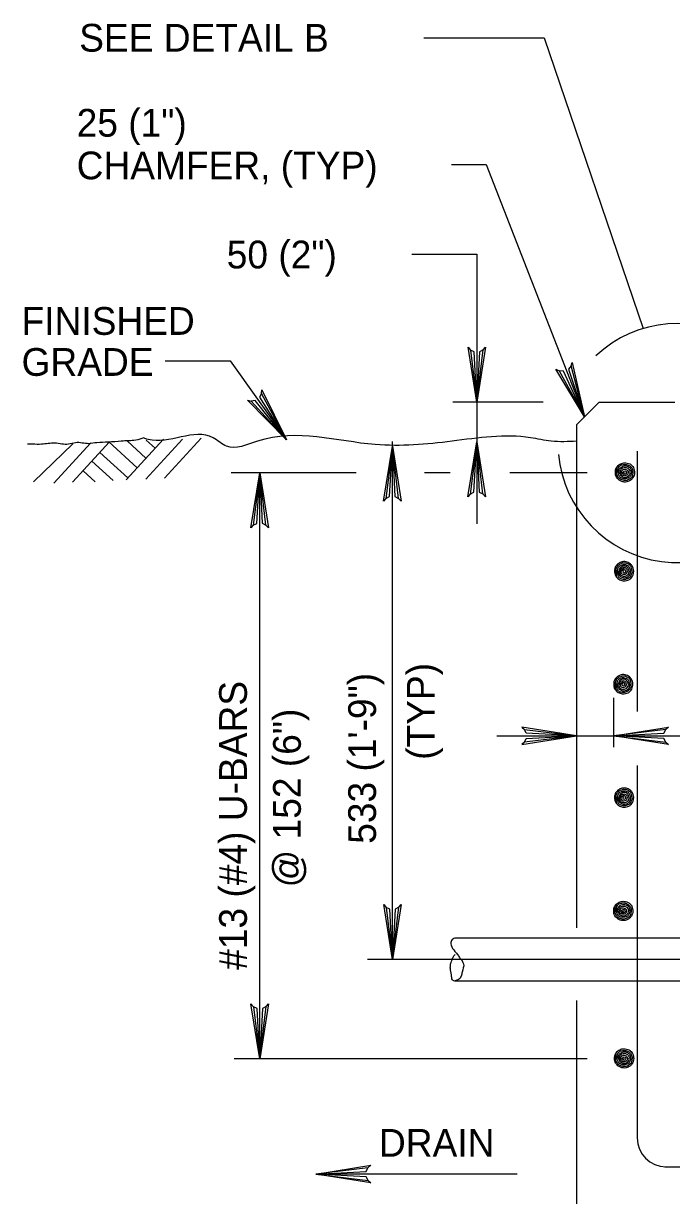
# Model space of a CAD drawing. Extents: x 638455 to 640199, y 298558 to 299152.
# Drawn here: x 638543.6 to 638622.1, y 298702.3 to 298844.2 of the extents above; entities that cross this region are included whole.
import ezdxf

# ---------------------------------------------------------------- set-up
doc = ezdxf.new("R2010")
doc.units = 0
for name, color, linetype in [('1', 7, 'Continuous'), ('2', 7, 'Continuous'), ('3', 7, 'Continuous')]:
    doc.layers.add(name, color=color, linetype=linetype)

msp = doc.modelspace()

# ---------------------------------------------------------------- linework, layer by layer
at = {"layer": '1'}
msp.add_arc((638622.78, 298793.39), 14.46, 185.4387, 133.0087, dxfattribs=at)
at = {"layer": '2'}
for p, q in [((638592.11, 298842.42), (638606.65, 298842.42)), ((638606.65, 298842.42), (638618.63, 298807.24)), ((638595.46, 298827.12), (638599.64, 298827.12)), ((638599.64, 298827.12), (638611.55, 298796.56)), ((638590.63, 298816.24), (638598.49, 298816.24)), ((638598.49, 298816.24), (638598.49, 298798.33)), ((638560.78, 298803.33), (638568.64, 298803.33)), ((638568.64, 298803.33), (638575.46, 298793.78)), ((638606.53, 298798.33), (638595.61, 298798.33)), ((638610.59, 298795.6), (638613.33, 298798.33)), ((638613.33, 298798.33), (638622.49, 298798.33)), ((638610.59, 298795.6), (638610.59, 298734.74)), ((638544.84, 298788.71), (638549.58, 298793.3)), ((638547.31, 298788.55), (638551.79, 298793.44)), ((638549.57, 298788.65), (638554.04, 298793.54)), ((638553.94, 298793.54), (638557.4, 298790.38)), ((638556.06, 298788.94), (638560.56, 298793.86)), ((638556.2, 298793.64), (638558.45, 298791.58)), ((638558.44, 298789.04), (638562.87, 298793.88)), ((638558.48, 298793.74), (638559.55, 298792.76)), ((638560.69, 298789.14), (638565.13, 298793.98)), ((638588.29, 298730.89), (638588.29, 298793.59)), ((638552.87, 298792.26), (638556.25, 298789.17)), ((638617.91, 298792.41), (638617.91, 298760.91)), ((638551.91, 298791.21), (638554.48, 298788.86)), ((638550.83, 298790.03), (638552.3, 298788.69)), ((638583.92, 298789.78), (638568.78, 298789.78)), ((638572.22, 298718.88), (638572.22, 298789.78)), ((638595.27, 298789.78), (638592.17, 298789.78)), ((638611.86, 298789.78), (638602.49, 298789.78)), ((638615.07, 298762.55), (638615.07, 298756.61)), ((638600.94, 298757.98), (638615.07, 298757.98)), ((638615.07, 298757.98), (638634.48, 298757.98)), ((638617.91, 298754.37), (638617.91, 298709.3)), ((638630.69, 298733.5), (638595.84, 298733.5)), ((638630.69, 298733.5), (638599.56, 298733.5)), ((638590.79, 298730.89), (638585.29, 298730.89)), ((638626.91, 298730.89), (638590.79, 298730.89)), ((638630.69, 298728.28), (638595.84, 298728.28)), ((638630.69, 298728.28), (638599.56, 298728.28)), ((638610.59, 298725.94), (638610.59, 298697.04)), ((638611.86, 298718.88), (638569.13, 298718.88)), ((638621.25, 298705.81), (638725.26, 298705.81))]:
    msp.add_line(p, q, dxfattribs=at)
for points in [[(638599.29, 298804.66), (638598.83, 298804.43), (638598.49, 298798.33), (638599.29, 298804.66), (638599.57, 298804.99), (638598.49, 298798.33), (638598.19, 298804.42), (638597.74, 298804.64), (638598.49, 298798.33), (638597.44, 298804.99), (638597.74, 298804.64)], [(638609.93, 298802.73), (638609.59, 298802.34), (638611.55, 298796.56), (638609.93, 298802.73), (638610.06, 298803.13), (638611.55, 298796.56), (638609, 298802.1), (638608.49, 298802.13), (638611.55, 298796.56), (638608.08, 298802.34), (638608.49, 298802.13)], [(638572.43, 298799.39), (638572.2, 298798.93), (638575.46, 298793.78), (638572.43, 298799.39), (638572.47, 298799.82), (638575.46, 298793.78), (638571.68, 298798.56), (638571.18, 298798.47), (638575.46, 298793.78), (638570.73, 298798.58), (638571.18, 298798.47)], [(638598.49, 298798.33), (638598.49, 298783.62)], [(638597.7, 298787.22), (638598.16, 298787.45), (638598.49, 298793.55), (638597.7, 298787.22), (638597.42, 298786.89), (638598.49, 298793.55), (638598.8, 298787.46), (638599.25, 298787.24), (638598.49, 298793.55), (638599.55, 298786.89), (638599.25, 298787.24)], [(638587.49, 298786.67), (638587.95, 298786.91), (638588.29, 298793), (638587.49, 298786.67), (638587.22, 298786.35), (638588.29, 298793), (638588.59, 298786.91), (638589.04, 298786.69), (638588.29, 298793), (638589.34, 298786.35), (638589.04, 298786.69)], [(638571.43, 298783.45), (638571.88, 298783.68), (638572.22, 298789.78), (638571.43, 298783.45), (638571.15, 298783.12), (638572.22, 298789.78), (638572.52, 298783.69), (638572.98, 298783.47), (638572.22, 298789.78), (638573.28, 298783.12), (638572.98, 298783.47)], [(638604.26, 298757.18), (638604.5, 298757.64), (638610.59, 298757.98), (638604.26, 298757.18), (638603.94, 298756.9), (638610.59, 298757.98), (638604.5, 298758.28), (638604.28, 298758.73), (638610.59, 298757.98), (638603.94, 298759.03), (638604.28, 298758.73)], [(638621.4, 298757.18), (638621.16, 298757.64), (638615.07, 298757.98), (638621.4, 298757.18), (638621.72, 298756.9), (638615.07, 298757.98), (638621.16, 298758.28), (638621.38, 298758.73), (638615.07, 298757.98), (638621.72, 298759.03), (638621.38, 298758.73)], [(638589.08, 298737.22), (638588.62, 298736.98), (638588.29, 298730.89), (638589.08, 298737.22), (638589.36, 298737.54), (638588.29, 298730.89), (638587.99, 298736.98), (638587.53, 298737.2), (638588.29, 298730.89), (638587.23, 298737.54), (638587.53, 298737.2)], [(638573.01, 298725.21), (638572.56, 298724.98), (638572.22, 298718.88), (638573.01, 298725.21), (638573.29, 298725.54), (638572.22, 298718.88), (638571.92, 298724.97), (638571.47, 298725.19), (638572.22, 298718.88), (638571.16, 298725.54), (638571.47, 298725.19)], [(638585.35, 298704.15), (638585.11, 298704.6), (638579.02, 298704.94), (638585.35, 298704.15), (638585.67, 298703.87), (638579.02, 298704.94), (638585.11, 298705.24), (638585.33, 298705.69), (638579.02, 298704.94), (638585.67, 298706), (638585.33, 298705.69)], [(638603.41, 298704.94), (638585.99, 298704.94), (638579.02, 298704.94)]]:
    msp.add_lwpolyline(points, dxfattribs=at)
msp.add_arc((638621.4, 298709.3), 3.48, 180, 270, dxfattribs=at)
for points in [[(638610.61, 298793.62), (638607.51, 298793.62), (638605.02, 298794.04), (638595.51, 298793.62), (638586.21, 298793.21), (638571.94, 298793.62), (638568.22, 298793), (638566.57, 298794.04), (638558.71, 298793.83), (638558.17, 298794.01)], [(638616.44, 298789.85), (638616.38, 298789.73), (638616.29, 298789.75), (638616.27, 298789.93), (638616.43, 298790.03), (638616.63, 298789.93), (638616.62, 298789.75), (638616.51, 298789.64), (638616.29, 298789.62), (638616.14, 298789.73), (638616.06, 298789.92), (638616.17, 298790.17), (638616.41, 298790.22), (638616.68, 298790.15), (638616.82, 298789.97), (638616.8, 298789.69), (638616.67, 298789.51), (638616.43, 298789.44), (638616.22, 298789.48), (638616.04, 298789.59), (638615.96, 298789.78), (638615.92, 298790.02), (638615.97, 298790.24), (638616.18, 298790.39), (638616.5, 298790.45), (638616.85, 298790.3), (638617.02, 298790.06), (638617.02, 298789.73), (638616.91, 298789.45), (638616.67, 298789.27), (638616.29, 298789.24), (638616.01, 298789.4), (638615.85, 298789.66), (638615.75, 298789.93), (638615.8, 298790.26), (638616.01, 298790.49), (638616.33, 298790.63), (638616.84, 298790.55), (638617.15, 298790.27), (638617.22, 298789.89), (638617.15, 298789.51), (638616.93, 298789.21), (638616.64, 298789.09), (638616.18, 298789.1), (638615.82, 298789.31), (638615.65, 298789.62), (638615.6, 298789.94), (638615.63, 298790.22), (638615.74, 298790.53), (638616.04, 298790.74), (638616.52, 298790.81), (638616.95, 298790.69), (638617.26, 298790.4), (638617.39, 298790.05), (638617.36, 298789.61), (638617.22, 298789.19), (638616.98, 298789.02), (638616.55, 298788.86), (638616.11, 298788.93), (638615.81, 298789.07), (638615.57, 298789.34), (638615.44, 298789.63), (638615.44, 298789.93), (638615.46, 298790.26), (638615.53, 298790.57), (638615.69, 298790.74), (638615.93, 298790.89), (638616.17, 298790.98), (638616.41, 298791.02), (638616.71, 298790.97), (638617.02, 298790.88), (638617.29, 298790.68), (638617.47, 298790.43), (638617.56, 298790.12), (638617.6, 298789.82), (638617.54, 298789.48), (638617.41, 298789.21), (638617.2, 298788.96), (638616.93, 298788.79), (638616.67, 298788.7), (638616.36, 298788.68), (638615.99, 298788.77), (638615.69, 298788.96), (638615.5, 298789.16), (638615.35, 298789.41), (638615.29, 298789.67), (638615.28, 298789.97), (638615.35, 298790.3), (638615.44, 298790.46), (638615.65, 298790.68)], [(638616.33, 298777.88), (638616.28, 298778), (638616.19, 298777.99), (638616.17, 298777.8), (638616.33, 298777.71), (638616.53, 298777.8), (638616.52, 298777.99), (638616.41, 298778.1), (638616.19, 298778.12), (638616.04, 298778), (638615.96, 298777.81), (638616.07, 298777.56), (638616.31, 298777.51), (638616.58, 298777.59), (638616.72, 298777.76), (638616.71, 298778.04), (638616.57, 298778.23), (638616.33, 298778.29), (638616.12, 298778.25), (638615.94, 298778.14), (638615.86, 298777.96), (638615.82, 298777.72), (638615.87, 298777.49), (638616.08, 298777.35), (638616.4, 298777.29), (638616.75, 298777.43), (638616.92, 298777.67), (638616.92, 298778), (638616.81, 298778.28), (638616.57, 298778.47), (638616.19, 298778.49), (638615.92, 298778.34), (638615.75, 298778.08), (638615.65, 298777.8), (638615.7, 298777.48), (638615.92, 298777.24), (638616.23, 298777.11), (638616.74, 298777.19), (638617.05, 298777.47), (638617.12, 298777.85), (638617.05, 298778.23), (638616.83, 298778.52), (638616.54, 298778.64), (638616.08, 298778.63), (638615.72, 298778.42), (638615.54, 298778.12), (638615.5, 298777.79), (638615.53, 298777.51), (638615.64, 298777.21), (638615.94, 298776.99), (638616.42, 298776.93), (638616.85, 298777.05), (638617.16, 298777.34), (638617.3, 298777.69), (638617.26, 298778.13), (638617.12, 298778.54), (638616.88, 298778.72), (638616.46, 298778.87), (638616.01, 298778.81), (638615.71, 298778.67), (638615.47, 298778.39), (638615.34, 298778.11), (638615.34, 298777.8), (638615.36, 298777.48), (638615.43, 298777.17), (638615.59, 298776.99), (638615.83, 298776.84), (638616.07, 298776.75), (638616.31, 298776.72), (638616.62, 298776.76), (638616.92, 298776.86), (638617.19, 298777.05), (638617.37, 298777.3), (638617.46, 298777.62), (638617.5, 298777.91), (638617.44, 298778.25), (638617.32, 298778.52), (638617.1, 298778.77), (638616.83, 298778.94), (638616.57, 298779.04), (638616.26, 298779.05), (638615.89, 298778.96), (638615.59, 298778.77), (638615.4, 298778.58), (638615.25, 298778.33), (638615.19, 298778.06), (638615.18, 298777.76), (638615.25, 298777.43), (638615.34, 298777.28), (638615.54, 298777.05)], [(638616.24, 298764.2), (638616.18, 298764.32), (638616.09, 298764.3), (638616.07, 298764.12), (638616.23, 298764.02), (638616.43, 298764.12), (638616.42, 298764.3), (638616.31, 298764.42), (638616.09, 298764.43), (638615.94, 298764.32), (638615.86, 298764.13), (638615.97, 298763.88), (638616.21, 298763.83), (638616.48, 298763.9), (638616.62, 298764.08), (638616.6, 298764.36), (638616.47, 298764.54), (638616.23, 298764.61), (638616.02, 298764.57), (638615.84, 298764.46), (638615.76, 298764.27), (638615.72, 298764.03), (638615.77, 298763.81), (638615.98, 298763.67), (638616.3, 298763.6), (638616.65, 298763.74), (638616.83, 298763.99), (638616.83, 298764.32), (638616.71, 298764.6), (638616.47, 298764.78), (638616.09, 298764.81), (638615.82, 298764.66), (638615.65, 298764.39), (638615.55, 298764.12), (638615.6, 298763.79), (638615.82, 298763.56), (638616.13, 298763.43), (638616.64, 298763.5), (638616.95, 298763.78), (638617.02, 298764.17), (638616.95, 298764.54), (638616.74, 298764.84), (638616.44, 298764.96), (638615.98, 298764.95), (638615.62, 298764.74), (638615.45, 298764.43), (638615.4, 298764.11), (638615.43, 298763.83), (638615.54, 298763.52), (638615.84, 298763.31), (638616.32, 298763.24), (638616.75, 298763.36), (638617.07, 298763.66), (638617.19, 298764), (638617.16, 298764.44), (638617.02, 298764.86), (638616.78, 298765.03), (638616.35, 298765.19), (638615.91, 298765.12), (638615.61, 298764.98), (638615.37, 298764.71), (638615.25, 298764.42), (638615.25, 298764.12), (638615.26, 298763.79), (638615.34, 298763.48), (638615.49, 298763.31), (638615.73, 298763.16), (638615.97, 298763.07), (638616.21, 298763.03), (638616.52, 298763.08), (638616.83, 298763.18), (638617.09, 298763.37), (638617.27, 298763.62), (638617.36, 298763.93), (638617.4, 298764.23), (638617.34, 298764.57), (638617.22, 298764.84), (638617, 298765.09), (638616.74, 298765.26), (638616.47, 298765.36), (638616.16, 298765.37), (638615.79, 298765.28), (638615.49, 298765.09), (638615.3, 298764.89), (638615.15, 298764.64), (638615.09, 298764.38), (638615.09, 298764.08), (638615.15, 298763.74), (638615.25, 298763.59), (638615.45, 298763.37)], [(638616.33, 298750.49), (638616.28, 298750.6), (638616.19, 298750.59), (638616.17, 298750.41), (638616.33, 298750.31), (638616.53, 298750.41), (638616.52, 298750.59), (638616.41, 298750.7), (638616.19, 298750.72), (638616.04, 298750.6), (638615.96, 298750.42), (638616.07, 298750.17), (638616.31, 298750.11), (638616.58, 298750.19), (638616.72, 298750.36), (638616.71, 298750.65), (638616.57, 298750.83), (638616.33, 298750.9), (638616.12, 298750.85), (638615.94, 298750.75), (638615.86, 298750.56), (638615.82, 298750.32), (638615.87, 298750.1), (638616.08, 298749.95), (638616.4, 298749.89), (638616.75, 298750.04), (638616.92, 298750.28), (638616.92, 298750.6), (638616.81, 298750.89), (638616.57, 298751.07), (638616.19, 298751.1), (638615.92, 298750.94), (638615.75, 298750.68), (638615.65, 298750.41), (638615.7, 298750.08), (638615.92, 298749.85), (638616.23, 298749.71), (638616.74, 298749.79), (638617.05, 298750.07), (638617.12, 298750.45), (638617.05, 298750.83), (638616.83, 298751.13), (638616.54, 298751.25), (638616.08, 298751.24), (638615.72, 298751.03), (638615.54, 298750.72), (638615.5, 298750.4), (638615.53, 298750.11), (638615.64, 298749.81), (638615.94, 298749.6), (638616.42, 298749.53), (638616.85, 298749.65), (638617.16, 298749.95), (638617.3, 298750.29), (638617.26, 298750.74), (638617.12, 298751.15), (638616.88, 298751.32), (638616.46, 298751.48), (638616.01, 298751.41), (638615.71, 298751.27), (638615.47, 298751), (638615.34, 298750.71), (638615.34, 298750.41), (638615.36, 298750.08), (638615.43, 298749.77), (638615.59, 298749.6), (638615.83, 298749.45), (638616.07, 298749.36), (638616.31, 298749.32), (638616.62, 298749.36), (638616.92, 298749.46), (638617.19, 298749.66), (638617.37, 298749.91), (638617.46, 298750.22), (638617.5, 298750.52), (638617.44, 298750.85), (638617.32, 298751.13), (638617.1, 298751.38), (638616.83, 298751.55), (638616.57, 298751.64), (638616.26, 298751.65), (638615.89, 298751.57), (638615.59, 298751.38), (638615.4, 298751.18), (638615.25, 298750.93), (638615.19, 298750.67), (638615.18, 298750.36), (638615.25, 298750.04), (638615.34, 298749.88), (638615.54, 298749.66)], [(638616.24, 298736.77), (638616.18, 298736.66), (638616.09, 298736.67), (638616.07, 298736.86), (638616.23, 298736.95), (638616.43, 298736.86), (638616.42, 298736.67), (638616.31, 298736.56), (638616.09, 298736.54), (638615.94, 298736.66), (638615.86, 298736.85), (638615.97, 298737.1), (638616.21, 298737.15), (638616.48, 298737.07), (638616.62, 298736.9), (638616.6, 298736.62), (638616.47, 298736.43), (638616.23, 298736.37), (638616.02, 298736.41), (638615.84, 298736.52), (638615.76, 298736.7), (638615.72, 298736.95), (638615.77, 298737.17), (638615.98, 298737.31), (638616.3, 298737.37), (638616.65, 298737.23), (638616.83, 298736.99), (638616.83, 298736.66), (638616.71, 298736.38), (638616.47, 298736.19), (638616.09, 298736.17), (638615.82, 298736.32), (638615.65, 298736.58), (638615.55, 298736.86), (638615.6, 298737.19), (638615.82, 298737.42), (638616.13, 298737.55), (638616.64, 298737.47), (638616.95, 298737.2), (638617.02, 298736.81), (638616.95, 298736.43), (638616.74, 298736.14), (638616.44, 298736.02), (638615.98, 298736.03), (638615.62, 298736.23), (638615.45, 298736.54), (638615.4, 298736.87), (638615.43, 298737.15), (638615.54, 298737.45), (638615.84, 298737.67), (638616.32, 298737.74), (638616.75, 298737.61), (638617.07, 298737.32), (638617.19, 298736.97), (638617.16, 298736.53), (638617.02, 298736.12), (638616.78, 298735.94), (638616.35, 298735.79), (638615.91, 298735.85), (638615.61, 298736), (638615.37, 298736.27), (638615.25, 298736.55), (638615.25, 298736.86), (638615.26, 298737.19), (638615.34, 298737.49), (638615.49, 298737.67), (638615.73, 298737.82), (638615.97, 298737.91), (638616.21, 298737.94), (638616.52, 298737.9), (638616.83, 298737.8), (638617.09, 298737.61), (638617.27, 298737.36), (638617.36, 298737.04), (638617.4, 298736.75), (638617.34, 298736.41), (638617.22, 298736.14), (638617, 298735.89), (638616.74, 298735.72), (638616.47, 298735.62), (638616.16, 298735.61), (638615.79, 298735.7), (638615.49, 298735.89), (638615.3, 298736.08), (638615.15, 298736.33), (638615.09, 298736.6), (638615.09, 298736.9), (638615.15, 298737.23), (638615.25, 298737.38), (638615.45, 298737.61)], [(638595.84, 298733.5), (638595.44, 298733.21), (638595.4, 298732.65), (638595.85, 298731.88), (638596.22, 298731.45), (638596.47, 298731.06), (638596.9, 298730.37), (638596.73, 298729.38), (638596.6, 298728.87), (638596.3, 298728.48), (638595.88, 298728.31), (638595.84, 298728.28)], [(638595.84, 298728.28), (638595.64, 298728.35), (638595.45, 298728.86), (638595.39, 298729.28), (638595.31, 298729.68), (638595.31, 298730.11), (638595.39, 298730.55), (638595.51, 298730.85), (638595.64, 298731.2), (638595.7, 298731.27), (638595.77, 298731.38), (638595.9, 298731.5)], [(638616.33, 298718.94), (638616.28, 298718.82), (638616.19, 298718.83), (638616.17, 298719.01), (638616.33, 298719.11), (638616.53, 298719.01), (638616.52, 298718.83), (638616.41, 298718.72), (638616.19, 298718.7), (638616.04, 298718.82), (638615.96, 298719), (638616.07, 298719.25), (638616.31, 298719.31), (638616.58, 298719.23), (638616.72, 298719.06), (638616.71, 298718.77), (638616.57, 298718.59), (638616.33, 298718.52), (638616.12, 298718.57), (638615.94, 298718.68), (638615.86, 298718.86), (638615.82, 298719.1), (638615.87, 298719.33), (638616.08, 298719.47), (638616.4, 298719.53), (638616.75, 298719.39), (638616.92, 298719.15), (638616.92, 298718.82), (638616.81, 298718.54), (638616.57, 298718.35), (638616.19, 298718.33), (638615.92, 298718.48), (638615.75, 298718.74), (638615.65, 298719.01), (638615.7, 298719.34), (638615.92, 298719.58), (638616.23, 298719.71), (638616.74, 298719.63), (638617.05, 298719.35), (638617.12, 298718.97), (638617.05, 298718.59), (638616.83, 298718.3), (638616.54, 298718.18), (638616.08, 298718.19), (638615.72, 298718.39), (638615.54, 298718.7), (638615.5, 298719.03), (638615.53, 298719.31), (638615.64, 298719.61), (638615.94, 298719.83), (638616.42, 298719.89), (638616.85, 298719.77), (638617.16, 298719.48), (638617.3, 298719.13), (638617.26, 298718.69), (638617.12, 298718.27), (638616.88, 298718.1), (638616.46, 298717.95), (638616.01, 298718.01), (638615.71, 298718.15), (638615.47, 298718.43), (638615.34, 298718.71), (638615.34, 298719.01), (638615.36, 298719.34), (638615.43, 298719.65), (638615.59, 298719.83), (638615.83, 298719.98), (638616.07, 298720.07), (638616.31, 298720.1), (638616.62, 298720.06), (638616.92, 298719.96), (638617.19, 298719.76), (638617.37, 298719.51), (638617.46, 298719.2), (638617.5, 298718.91), (638617.44, 298718.57), (638617.32, 298718.3), (638617.1, 298718.05), (638616.83, 298717.88), (638616.57, 298717.78), (638616.26, 298717.77), (638615.89, 298717.86), (638615.59, 298718.05), (638615.4, 298718.24), (638615.25, 298718.49), (638615.19, 298718.75), (638615.18, 298719.06), (638615.25, 298719.39), (638615.34, 298719.54), (638615.54, 298719.76)]]:
    msp.add_spline(points, degree=3, dxfattribs=at)
at = {"layer": '3'}
msp.add_spline([(638558.17, 298794.01), (638557.21, 298793.75), (638555.46, 298793.63), (638553.89, 298793.5), (638552.51, 298793.44), (638551.51, 298793.32), (638549.94, 298793.44), (638549.06, 298793.25), (638547.43, 298793.38), (638545.8, 298793.25), (638544.73, 298793.25), (638544.11, 298793.25)], degree=3, dxfattribs=at)

# ---------------------------------------------------------------- texts
for s, p in [('SEE DETAIL B', (638550.37, 298840.76)), ('25 (1")', (638550.06, 298830.47)), ('CHAMFER, (TYP)', (638550.06, 298825.31)), ('50 (2")', (638568.23, 298814.53)), ('FINISHED', (638543.39, 298806.49)), ('GRADE', (638543.39, 298801.53)), ('DRAIN', (638586.66, 298707.03))]:
    msp.add_text(s, height=3.36, dxfattribs=at).set_placement(p)
for s, p in [('(TYP)', (638593.4, 298755.06)), ('533 (1\'-9")', (638586.3, 298744.9)), ('#13 (#4) U-BARS', (638570.67, 298729.65)), ('@ 152 (6")', (638577.2, 298739.62))]:
    msp.add_text(s, height=3.36, rotation=90, dxfattribs=at).set_placement(p)

doc.saveas('drawing.dxf')
